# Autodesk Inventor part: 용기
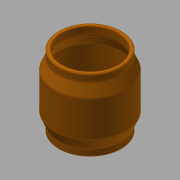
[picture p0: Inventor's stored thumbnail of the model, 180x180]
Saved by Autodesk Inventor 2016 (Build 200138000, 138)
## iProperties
Created: 2018-01
Part Number: 용기
Material: ABS 플라스틱
Document SubType Name: Modeling
Designer: mduedu
Density: 1 g/cm^3
Appearance: 주황색
Author: mduedu
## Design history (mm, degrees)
sketch "스케치1"
  geometry: L1 (0, 0)-(-35, 0); L2 (-35, 0)-(-35, 8); L3 (-35, 8)-(-40, 20); L4 (-40, 20)-(-40, 60); L5 (-40, 60)-(-35, 72); L6 (-35, 72)-(-35, 80); L7 (-35, 80)-(0, 80); L8 (0, 80)-(0, 0)
  constraints: 16 end point, 3 collinear, 3 parallel, 1 horizontal, 1 perpendicular
  dimensions: "d0" = 8 distance of L1.end L2.end; "d2" = 70 diameter of L2 L8; "d3" = 20 distance from line of L3.end L1; "d4" = 60 distance from line of L4.end L1; "d5" = 20 distance from line of L4.end L7; "d6" = 80 diameter of L4 L8
revolve "회전1" sketch "스케치1" stored, may be unused: angle "d7" = 90 deg
fillet "모깎기1" dims "d8" = 3
feature "쉘1" dims "d9" = 4
fillet "모깎기2" dims "d10" = 1
chamfer "모따기1" distance "d11" = 0.5; stored, may be unused: second distance "d12" = 2, angle "d13" = 45 deg
node "솔리드1"
